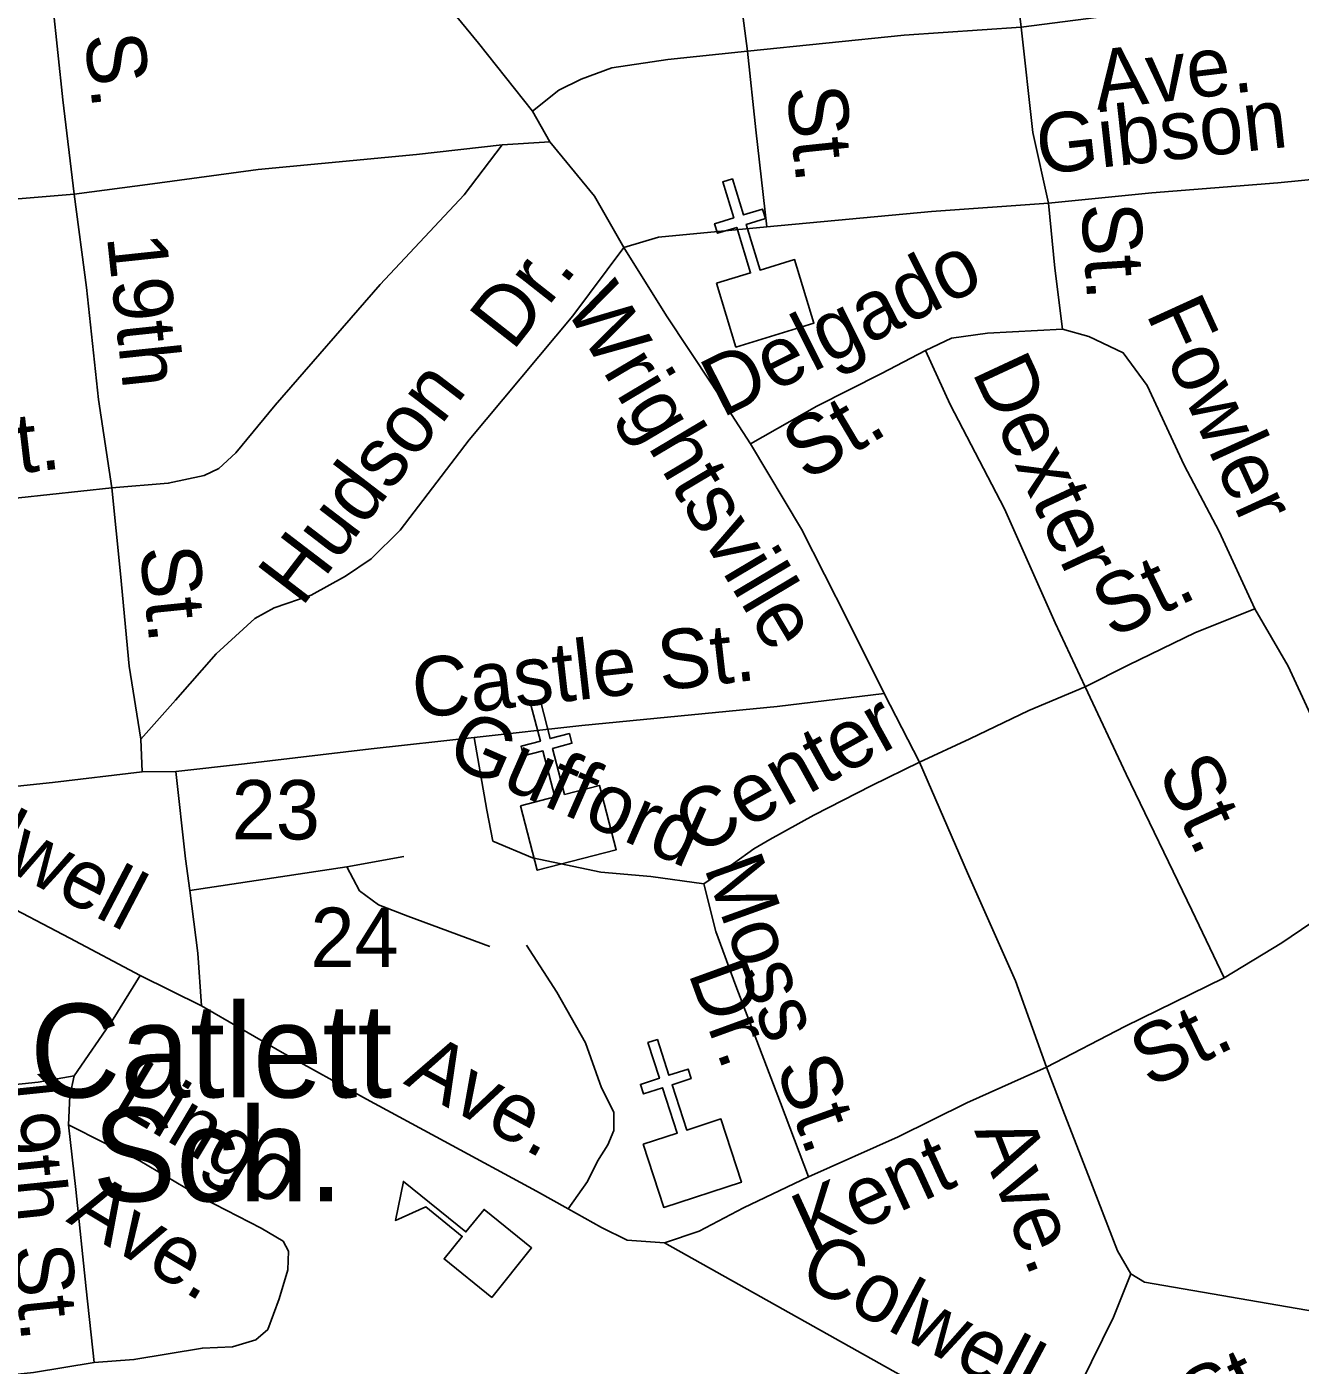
# Model space of a CAD drawing. Extents: x 2290055 to 2389491, y 66597 to 237875.
# Drawn here: x 2324958 to 2326996, y 175420 to 177562 of the extents above; entities that cross this region are included whole.
import ezdxf

# ---------------------------------------------------------------- set-up
doc = ezdxf.new("R2010")
doc.units = 0
for name, color, linetype in [('Exist Cultural Church CELL', 7, 'Continuous'), ('Exist Cultural Educational Facility High CELL', 7, 'Continuous'), ('Exist Cultural Educational Facility High Label', 7, 'Continuous'), ('Exist Road Non-System Type 51', 7, 'Continuous'), ('Exist Road Non-System Type 51 Label', 7, 'Continuous'), ('Exist Road Secondary Type 51 Attributed', 7, 'Continuous'), ('Exist Road Secondary Type 51 Label', 7, 'Continuous')]:
    doc.layers.add(name, color=color, linetype=linetype)

msp = doc.modelspace()

# ---------------------------------------------------------------- linework, layer by layer
at = {"layer": 'Exist Cultural Church CELL'}
for points in [[(2326061.8, 177151.4), (2326116.2, 177168.1), (2326094, 177240.9), (2326063.4, 177231.6), (2326058.7, 177246.8), (2326089.3, 177256.2), (2326071.8, 177313.7), (2326087.1, 177318.4), (2326104.7, 177260.8), (2326135.3, 177270.2), (2326139.9, 177254.9), (2326109.3, 177245.6), (2326131.5, 177172.7), (2326186.7, 177189.4), (2326217.7, 177087.6), (2326092.8, 177049.5)], [(2325748.1, 176315.2), (2325803.1, 176329.6), (2325784, 176403.3), (2325753, 176395.3), (2325749, 176410.7), (2325780, 176418.8), (2325764.9, 176477), (2325780.4, 176481), (2325795.5, 176422.8), (2325826.5, 176430.8), (2325830.5, 176415.4), (2325799.5, 176407.3), (2325818.6, 176333.6), (2325874.5, 176348), (2325901.2, 176244.9), (2325774.8, 176212.1)], [(2325944.6, 175774), (2325998.8, 175791.6), (2325975.4, 175864.1), (2325944.9, 175854.3), (2325940, 175869.5), (2325970.5, 175879.3), (2325952, 175936.5), (2325967.2, 175941.4), (2325985.7, 175884.2), (2326016.2, 175894), (2326021.1, 175878.8), (2325990.6, 175869), (2326014, 175796.5), (2326068.9, 175814.2), (2326101.6, 175712.9), (2325977.3, 175672.7)]]:
    msp.add_lwpolyline(points, close=True, dxfattribs=at)
at = {"layer": 'Exist Cultural Educational Facility High CELL'}
msp.add_lwpolyline([(2325702, 175528.8), (2325625.8, 175590.4), (2325654.8, 175626.2), (2325596.4, 175673.4), (2325548, 175652), (2325560.9, 175714.4), (2325660.8, 175633.6), (2325689.8, 175669.4), (2325765.9, 175607.8)], close=True, dxfattribs=at)
at = {"layer": 'Exist Road Non-System Type 51'}
for p, q in [((2326826.7, 177597), (2326549.1, 177561.3)), ((2325795, 177377.9), (2325767.1, 177427.1)), ((2325795, 177377.9), (2325719, 177373)), ((2326386.3, 176385.3), (2326330.1, 176495)), ((2325142.7, 176369.8), (2325140.6, 176421.9)), ((2325196.5, 176370), (2325142.7, 176369.8)), ((2325139.5, 176043.8), (2325237.6, 175995.5)), ((2326618.7, 175822), (2326589.7, 175897.1))]:
    msp.add_line(p, q, dxfattribs=at)
for points in [[(2326549.1, 177561.3), (2326515.8, 177840.9)], [(2326079.5, 177817.5), (2326091.4, 177673.9), (2326111.2, 177522.7)], [(2325767.1, 177427.1), (2325680.7, 177535.5), (2325579.7, 177659.5)], [(2325033.9, 177294), (2325016.1, 177445.2), (2324999.9, 177596.6)], [(2326549.1, 177561.3), (2326362.2, 177548.4), (2326111.2, 177522.7)], [(2326593.1, 177279.6), (2326568, 177392.7), (2326549.1, 177561.3)], [(2326111.2, 177522.7), (2325983.7, 177509.5), (2325894.3, 177496.1), (2325845.1, 177478.1), (2325809.7, 177460.6), (2325767.1, 177427.1)], [(2326111.2, 177522.7), (2326124.4, 177397.2), (2326142.3, 177241.7)], [(2325719, 177373), (2325581.8, 177357.7), (2325328.4, 177333.5), (2325159.3, 177310.8), (2325033.9, 177294)], [(2325719, 177373), (2325658.2, 177292.8), (2325523.7, 177149.3), (2325355.4, 176956.5), (2325292.5, 176879.9), (2325265.6, 176854.9), (2325241.8, 176844.1), (2325184.5, 176831.6), (2325094.5, 176824.1)], [(2325913.6, 177208.7), (2325866.3, 177290.8), (2325795, 177377.9)], [(2327288.9, 177345.2), (2327165.3, 177332.4), (2326960, 177312.2), (2326758.5, 177296.3), (2326593.1, 177279.6)], [(2325033.9, 177294), (2324886.4, 177281.9), (2324729.2, 177263.9)], [(2325094.5, 176824.1), (2325072.9, 176965.4), (2325053.9, 177144.8), (2325033.9, 177294)], [(2326593.1, 177279.6), (2326405.6, 177266.2), (2326142.3, 177241.7)], [(2326615.2, 177078.3), (2326603.1, 177175.9), (2326593.1, 177279.6)], [(2326142.3, 177241.7), (2325969, 177225), (2325913.6, 177208.7)], [(2325913.6, 177208.7), (2325831.9, 177099.5), (2325665.8, 176900.9), (2325555.4, 176756.4), (2325509.3, 176710.6), (2325468.3, 176683), (2325413.4, 176652.6), (2325354.2, 176632.2), (2325323, 176615.2), (2325261.3, 176558.6), (2325195.9, 176484.2), (2325140.6, 176421.9)], [(2326116, 176894.8), (2326054.5, 176990.1), (2325981.9, 177099.5), (2325913.6, 177208.7)], [(2326396.3, 177043.7), (2326437.5, 177063.4), (2326495.3, 177071.6), (2326615.2, 177078.3)], [(2326615.2, 177078.3), (2326657.6, 177066.2), (2326712.5, 177040.1), (2326750.7, 176987.8), (2326809.9, 176860.2), (2326865.9, 176754.1), (2326923, 176630.3)], [(2326116, 176894.8), (2326222, 176954.7), (2326325.9, 177007.1), (2326396.3, 177043.7)], [(2326651.6, 176505.7), (2326603.6, 176607.9), (2326522.5, 176790.7), (2326435.8, 176957.3), (2326396.3, 177043.7)], [(2326330.1, 176495), (2326271.3, 176612.7), (2326197.6, 176757.8), (2326116, 176894.8)], [(2325094.5, 176824.1), (2324945.2, 176808.4), (2324781.9, 176787.8)], [(2325140.6, 176421.9), (2325121.9, 176539), (2325108.2, 176686.8), (2325094.5, 176824.1)], [(2326651.6, 176505.7), (2326720.5, 176540.3), (2326828.3, 176592.8), (2326923, 176630.3)], [(2326923, 176630.3), (2326976.5, 176538.6), (2327044.4, 176391.3), (2327082.4, 176292.7), (2327088.3, 176242.7), (2327076.2, 176192.4), (2327044.1, 176149.1), (2326966.2, 176096.1), (2326874.2, 176040.3)], [(2326386.3, 176385.3), (2326466.9, 176422.3), (2326561.2, 176468), (2326651.6, 176505.7)], [(2326874.2, 176040.3), (2326822, 176148.2), (2326717.2, 176366.2), (2326651.6, 176505.7)], [(2326330.1, 176495), (2326158.9, 176474.1), (2325846.1, 176443.6), (2325674.1, 176424.6)], [(2325674.1, 176424.6), (2325509.2, 176406.3), (2325306.3, 176382.6), (2325196.5, 176370)], [(2325674.1, 176424.6), (2325694.1, 176308.6), (2325704, 176258.8), (2325767.1, 176232.2), (2325876.7, 176208.9), (2325956.4, 176202.3), (2326041.3, 176190.7)], [(2326041.3, 176190.7), (2326088.8, 176223.2), (2326121.7, 176246.5), (2326147.3, 176261.6), (2326217.7, 176300.5), (2326310, 176348.1), (2326386.3, 176385.3)], [(2326589.7, 175897.1), (2326540.3, 176035.3), (2326463.5, 176208.1), (2326386.3, 176385.3)], [(2325142.7, 176369.8), (2324999.3, 176352.4), (2324835.9, 176335.7)], [(2325218.9, 176179.7), (2325212.2, 176230.5), (2325196.5, 176370)], [(2324652.7, 176312.4), (2324722.4, 176267.2), (2324906.6, 176166.5), (2325027.2, 176103.4), (2325139.5, 176043.8)], [(2325470.5, 176217.8), (2325561.6, 176234)], [(2325218.9, 176179.7), (2325470.5, 176217.8)], [(2325470.5, 176217.8), (2325490.7, 176179.3), (2325521.1, 176157), (2325567.7, 176138.7), (2325699.3, 176090.1)], [(2325237.6, 175995.5), (2325232, 176079.3), (2325218.9, 176179.7)], [(2326208.7, 175721.8), (2326164, 175840.2), (2326092.6, 176027.4), (2326060.9, 176114.1), (2326041.3, 176190.7)], [(2325757.5, 176092.1), (2325806.3, 176017.2), (2325851.9, 175935.8), (2325877.9, 175864.2), (2325897.5, 175825.1), (2325897.5, 175795.8), (2325887.7, 175773), (2325871.4, 175746.9), (2325855.2, 175714.4), (2325824.4, 175670.4)], [(2325139.5, 176043.8), (2325096.4, 175973.8), (2325034, 175883.4)], [(2326874.2, 176040.3), (2326715.1, 175962.1), (2326589.7, 175897.1)], [(2325237.6, 175995.5), (2325366.6, 175920.5), (2325501.5, 175845.8), (2325626.2, 175778.9), (2325773.5, 175698.7), (2325824.4, 175670.4)], [(2325034, 175883.4), (2324976.3, 175873.3), (2324791.5, 175854.1)], [(2325034, 175883.4), (2325027, 175851.3), (2325024.9, 175805)], [(2326208.7, 175721.8), (2326352.3, 175785.6), (2326462, 175839.9), (2326589.7, 175897.1)], [(2326724.9, 175566.4), (2326703.4, 175603.3), (2326656.7, 175723.5), (2326618.7, 175822)], [(2325065.9, 175424.6), (2325129.7, 175429.1), (2325239.3, 175447.5), (2325287.1, 175449.4), (2325324.7, 175460.7), (2325344.1, 175477.6), (2325362.2, 175526.2), (2325376.1, 175573), (2325376.9, 175602.9), (2325368.4, 175618.7), (2325333.4, 175639.3), (2325239.6, 175687.4), (2325139.1, 175747.4), (2325024.9, 175805)], [(2325024.9, 175805), (2325036.9, 175701.4), (2325053.4, 175542.2), (2325065.9, 175424.6)], [(2325978.4, 175616), (2326034, 175634.9), (2326104.7, 175671.8), (2326208.7, 175721.8)], [(2325824.4, 175670.4), (2325877.8, 175640.8), (2325918.7, 175620.4), (2325978.4, 175616)], [(2325978.4, 175616), (2326559.8, 175290.4)], [(2325065.9, 175424.6), (2324968.7, 175408.6), (2324837.2, 175394.7)]]:
    msp.add_lwpolyline(points, dxfattribs=at)
at = {"layer": 'Exist Road Secondary Type 51 Attributed'}
msp.add_lwpolyline([(2325231.7, 174980.6), (2325370.6, 175003.8), (2325500.7, 175061.7), (2325651.6, 175153.2), (2325744.7, 175183.7), (2325810.5, 175198.2), (2325924.5, 175203), (2325988.7, 175199.8), (2326245.6, 175146.8), (2326349.9, 175143.6), (2326454.3, 175174.1), (2326507.2, 175206.2), (2326582.7, 175278.5), (2326608.4, 175317.1), (2326696.7, 175497), (2326724.9, 175566.4), (2326746.5, 175553.1), (2327541.4, 175415.8)], dxfattribs=at)

# ---------------------------------------------------------------- texts
at = {"layer": 'Exist Cultural Educational Facility High Label'}
for s, p in [('Catlett', (2324963.2, 175848.6)), ('Sch.', (2325063.3, 175682.3))]:
    msp.add_text(s, height=150, dxfattribs=at).set_placement(p)
at = {"layer": 'Exist Road Non-System Type 51 Label'}
for s, rotation, p in [('S.', 276.4509, (2325050.3, 177548.1)), ('Ave.', 6.7847, (2326670.9, 177429.1)), ('St.', 275.9872, (2326173.7, 177464.1)), ('Gibson', 6.3257, (2326578.5, 177325.5)), ('St.', 273.7273, (2326645, 177277.7)), ('19th', 276.0486, (2325086.3, 177226.5)), ('Dr.', 51.8284, (2325735.7, 177041.4)), ('Delgado', 26.7377, (2326070.5, 176935.4)), ('Wrightsville', 300.7837, (2325817.4, 177114.2)), ('Fowler', 294.5419, (2326748.2, 177103.2)), ('Dexter', 294.9667, (2326469.7, 177009.8)), ('Hudson', 52.607, (2325398.1, 176631.7)), ('St.', 30.623, (2326205.2, 176833.4)), ('St.', 6.7251, (2324861, 176837.1)), ('St.', 275.8625, (2325138.8, 176727.8)), ('St.', 25.9589, (2326694.1, 176582.2)), ('Castle St.', 6.4665, (2325580, 176454.9)), ('Center', 28.9349, (2326029.2, 176234.1)), ('Gufford', 336.2697, (2325625.3, 176385.6)), ('St.', 294.9651, (2326766.9, 176371.3)), ('Colwell', 332.3688, (2324751.8, 176303.1)), ('Moss St.', 289.768, (2326041.2, 176216.8)), ('Dr.', 289.9888, (2326015.8, 176048.1)), ('St.', 26.1751, (2326754.9, 175862.4)), ('Ave.', 331.4379, (2325559.2, 175871.4)), ('Lingo', 329.156, (2325093.4, 175832.1)), ('19th St.', 275.9095, (2324905.3, 175891.3)), ('Ave.', 291.2546, (2326473.8, 175795.8)), ('Kent', 24.6321, (2326212.4, 175599.6)), ('Ave.', 329.156, (2325019.4, 175650.9)), ('Colwell', 331.9564, (2326189, 175554.2))]:
    msp.add_text(s, height=95, rotation=rotation, dxfattribs=at).set_placement(p)
for s, p in [('23', (2325285.9, 176261.5)), ('24', (2325412, 176057.4))]:
    msp.add_text(s, height=95, dxfattribs=at).set_placement(p)
at = {"layer": 'Exist Road Secondary Type 51 Label'}
msp.add_text('St.', height=95, rotation=26.7461, dxfattribs=at).set_placement((2326834.1, 175313.7))

doc.saveas('drawing.dxf')
